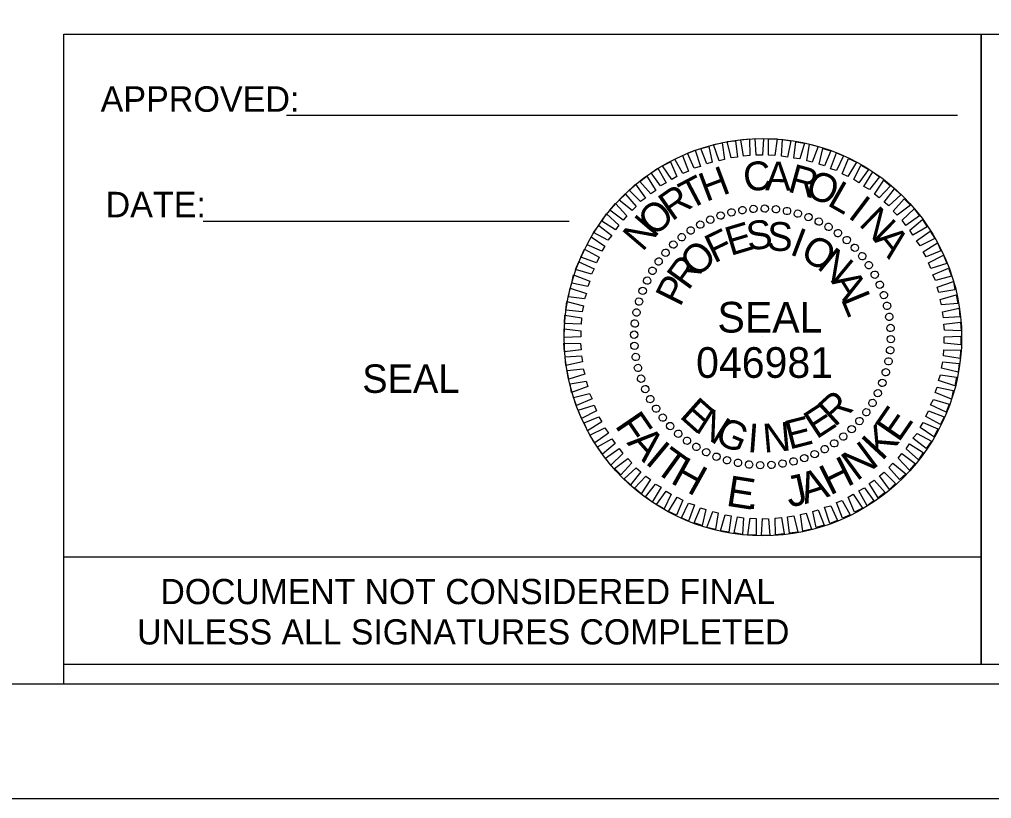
# Model space of a CAD drawing. Extents: x 2157572 to 5059327, y 715220 to 1674494.
# Drawn here: x 2166357 to 2168053, y 722289 to 723649 of the extents above; entities that cross this region are included whole.
import ezdxf

# ---------------------------------------------------------------- set-up
doc = ezdxf.new("R2010")
doc.units = 0
for name, color, linetype in [('Exist Road Primary NC Mileage Hundredths English Label', 7, 'Continuous'), ('Exist Road Secondary Type 51 Divided Label', 7, 'Continuous'), ('Exist Road Secondary Type 51 Undivided 3 Lane Attributed', 7, 'Continuous'), ('Map Preparation County Base Legend Wide River or Creek', 7, 'Continuous'), ('Map Preparation County North Arrow White Shapes', 7, 'Continuous')]:
    doc.layers.add(name, color=color, linetype=linetype)

# ---------------------------------------------------------------- blocks, each defined once
blk = doc.blocks.new('STICKER EXCEPTION CERTIFICATION')
at = {"layer": 'Map Preparation County Base Legend Wide River or Creek'}
for p, q in [((0, -0.188), (0, 0)), ((0, 0), (1.6003, 0)), ((1.6003, -0.0001), (1.6003, -0.1881)), ((1.6003, -0.188), (0, -0.188))]:
    blk.add_line(p, q, dxfattribs=at)
for s, p in [('DOCUMENT NOT CONSIDERED FINAL', (0.1686, -0.0828)), ('UNLESS ALL SIGNATURES COMPLETED', (0.128, -0.1532))]:
    blk.add_text(s, height=0.044, dxfattribs=at).set_placement(p)

msp = doc.modelspace()

# ---------------------------------------------------------------- linework, layer by layer
at = {"layer": 'Exist Road Primary NC Mileage Hundredths English Label'}
for p, q in [((2167580, 723306.6), (2167580, 723306.6)), ((2167598.8, 723311.9), (2167598.8, 723311.9)), ((2167618.4, 723315.5), (2167618.4, 723315.5)), ((2167637.6, 723318.2), (2167637.6, 723318.2)), ((2167657.3, 723318.6), (2167657.3, 723318.6)), ((2167676.9, 723317.3), (2167676.9, 723317.3)), ((2167696.1, 723314.2), (2167696.1, 723314.2)), ((2167714.9, 723310.2), (2167714.9, 723310.2)), ((2167544.8, 723290.5), (2167544.8, 723290.5)), ((2167562.2, 723299.4), (2167562.2, 723299.4)), ((2167733.6, 723303.9), (2167733.6, 723303.9)), ((2167751.5, 723295.9), (2167751.5, 723295.9)), ((2167527.8, 723280.2), (2167527.8, 723280.2)), ((2167768.9, 723286.9), (2167768.9, 723286.9)), ((2167785, 723275.8), (2167785, 723275.8)), ((2167497.4, 723255.7), (2167497.4, 723255.7)), ((2167512.2, 723269.1), (2167512.2, 723269.1)), ((2167800.6, 723263.7), (2167800.6, 723263.7)), ((2167484, 723241.8), (2167484, 723241.8)), ((2167814.4, 723250.3), (2167814.4, 723250.3)), ((2167472, 723226.2), (2167472, 723226.2)), ((2167827.8, 723235.6), (2167827.8, 723235.6)), ((2167839, 723220), (2167839, 723220)), ((2167460.8, 723210.1), (2167460.8, 723210.1)), ((2167849.3, 723203), (2167849.3, 723203)), ((2167451.9, 723192.7), (2167451.9, 723192.7)), ((2167443.9, 723174.9), (2167443.9, 723174.9)), ((2167858.2, 723185.6), (2167858.2, 723185.6)), ((2167437.6, 723156.1), (2167437.6, 723156.1)), ((2167865.3, 723167.7), (2167865.3, 723167.7)), ((2167433.6, 723137.4), (2167433.6, 723137.4)), ((2167870.7, 723149), (2167870.7, 723149)), ((2167430.5, 723118.2), (2167430.5, 723118.2)), ((2167874.3, 723129.3), (2167874.3, 723129.3)), ((2167876.9, 723110.1), (2167876.9, 723110.1)), ((2167429.1, 723098.5), (2167429.1, 723098.5)), ((2167653.3, 723094.5), (2167653.3, 723094.5)), ((2167877.4, 723090.5), (2167877.4, 723090.5)), ((2167429.6, 723078.9), (2167429.6, 723078.9)), ((2167876, 723070.8), (2167876, 723070.8)), ((2167432.2, 723059.7), (2167432.2, 723059.7)), ((2167872.9, 723051.6), (2167872.9, 723051.6)), ((2167435.8, 723040), (2167435.8, 723040)), ((2167441.2, 723021.3), (2167441.2, 723021.3)), ((2167868.9, 723032.9), (2167868.9, 723032.9)), ((2167448.3, 723003.4), (2167448.3, 723003.4)), ((2167862.7, 723014.1), (2167862.7, 723014.1)), ((2167457.2, 722986), (2167457.2, 722986)), ((2167854.6, 722996.3), (2167854.6, 722996.3)), ((2167467.5, 722969), (2167467.5, 722969)), ((2167845.7, 722978.9), (2167845.7, 722978.9)), ((2167478.7, 722953.4), (2167478.7, 722953.4)), ((2167834.5, 722962.8), (2167834.5, 722962.8)), ((2167492.1, 722938.7), (2167492.1, 722938.7)), ((2167809.1, 722933.3), (2167809.1, 722933.3)), ((2167822.5, 722947.2), (2167822.5, 722947.2)), ((2167505.9, 722925.3), (2167505.9, 722925.3)), ((2167794.3, 722919.9), (2167794.3, 722919.9)), ((2167521.5, 722913.2), (2167521.5, 722913.2)), ((2167537.6, 722902.1), (2167537.6, 722902.1)), ((2167761.7, 722898.5), (2167761.7, 722898.5)), ((2167778.7, 722908.8), (2167778.7, 722908.8)), ((2167555, 722893.1), (2167555, 722893.1)), ((2167572.9, 722885.1), (2167572.9, 722885.1)), ((2167726.5, 722882.4), (2167726.5, 722882.4)), ((2167744.3, 722889.6), (2167744.3, 722889.6)), ((2167591.6, 722878.9), (2167591.6, 722878.9)), ((2167610.4, 722874.8), (2167610.4, 722874.8)), ((2167629.6, 722871.7), (2167629.6, 722871.7)), ((2167649.2, 722870.4), (2167649.2, 722870.4)), ((2167668.9, 722870.8), (2167668.9, 722870.8)), ((2167688.1, 722873.5), (2167688.1, 722873.5)), ((2167707.7, 722877.1), (2167707.7, 722877.1))]:
    msp.add_line(p, q, dxfattribs=at)
for points in [[(2167642.5, 723411.9), (2167640.3, 723441), (2167655, 723440.5), (2167653.3, 723411.5)], [(2167664, 723411.5), (2167664, 723440.5), (2167678.7, 723440.1), (2167674.7, 723411.1)], [(2167555.9, 723396.3), (2167545.7, 723423.1), (2167559.5, 723427.1), (2167565.3, 723399.4)], [(2167577.4, 723402.1), (2167568, 723430.3), (2167583.2, 723433.4), (2167586.7, 723404.4)], [(2167598.8, 723407), (2167591.6, 723435.6), (2167606.4, 723437), (2167609.5, 723408.4)], [(2167620.2, 723409.7), (2167615.3, 723438.3), (2167630.5, 723440.1), (2167630.9, 723411.1)], [(2167686.3, 723410.2), (2167688.1, 723439.2), (2167702.8, 723436.5), (2167697, 723408.4)], [(2167707.7, 723406.6), (2167711.7, 723435.2), (2167726.5, 723432.9), (2167718.4, 723405.3)], [(2167730.5, 723401.7), (2167735, 723430.7), (2167750.1, 723427.1), (2167739.9, 723399.4)], [(2167751.9, 723395.9), (2167758.6, 723423.6), (2167772.5, 723419.1), (2167761.3, 723392.8)], [(2167514.4, 723379.8), (2167500.1, 723404.8), (2167514, 723411.1), (2167524.2, 723383.8)], [(2167534, 723389.2), (2167522.4, 723415.1), (2167535.8, 723420.4), (2167545.2, 723391.9)], [(2167772, 723387.8), (2167782.3, 723416), (2167794.8, 723410.6), (2167782.3, 723384.7)], [(2167495.2, 723369.1), (2167478.7, 723393.2), (2167492.5, 723400.3), (2167503.7, 723374.4)], [(2167792.1, 723379.4), (2167803.3, 723405.7), (2167817.1, 723399.4), (2167801.9, 723374.4)], [(2167812.6, 723369.1), (2167824.7, 723394.5), (2167838.1, 723386.9), (2167821.1, 723363.7)], [(2167458.6, 723344.5), (2167439.4, 723366), (2167451.4, 723375.3), (2167467.1, 723350.3)], [(2167475.6, 723357.9), (2167459, 723380.7), (2167470.6, 723389.2), (2167485.4, 723363.3)], [(2167830.1, 723357), (2167845.7, 723382.9), (2167857.3, 723373.6), (2167839.9, 723351.7)], [(2167440.7, 723330.7), (2167421.1, 723350.3), (2167431.8, 723361.1), (2167449.2, 723336.9)], [(2167848.4, 723343.6), (2167864.9, 723368.2), (2167876.5, 723358.4), (2167856.8, 723337.4)], [(2167426, 723315.1), (2167403.2, 723333.4), (2167414.4, 723343.6), (2167433.1, 723322.2)], [(2167865.3, 723329.8), (2167883.6, 723353), (2167894.4, 723342.3), (2167873.8, 723323.1)], [(2167410.4, 723298.1), (2167387.2, 723315.5), (2167397, 723327.1), (2167416.6, 723306.1)], [(2167881.4, 723314.2), (2167900.6, 723335.2), (2167911.3, 723324.4), (2167888.1, 723307)], [(2167397, 723281.1), (2167372.9, 723296.3), (2167381.3, 723309.3), (2167402.8, 723289.6)], [(2167897, 723298.1), (2167917.6, 723318.2), (2167926.9, 723306.1), (2167903.3, 723289.2)], [(2167383.6, 723263.3), (2167358.6, 723276.7), (2167367.5, 723289.2), (2167390.7, 723271.3)], [(2167910.4, 723280.7), (2167932.3, 723299.4), (2167940.8, 723286.5), (2167915.8, 723272.2)], [(2167922, 723262.4), (2167945.7, 723279.3), (2167954.2, 723266), (2167928.3, 723253.5)], [(2167372.9, 723244.1), (2167347.4, 723255.2), (2167354.1, 723269.1), (2167378.2, 723252.6)], [(2167933.6, 723242.7), (2167958.6, 723258.4), (2167964.4, 723244.5), (2167939, 723234.3)], [(2167363.9, 723223.5), (2167336.3, 723233.8), (2167343, 723247.6), (2167368.4, 723233.4)], [(2167942.6, 723223.5), (2167968.9, 723236.9), (2167974.7, 723222.6), (2167947, 723213.7)], [(2167355, 723203.9), (2167327.3, 723211.9), (2167333.1, 723225.8), (2167359.9, 723213.3)], [(2167348.3, 723182.5), (2167320.6, 723188.3), (2167323.8, 723203), (2167351.9, 723191.8)], [(2167950.6, 723202.6), (2167977.8, 723214.2), (2167982.8, 723200.3), (2167955.1, 723193.2)], [(2167957.8, 723181.1), (2167986.3, 723191.4), (2167989, 723176.7), (2167960.9, 723171.7)], [(2167342.5, 723161), (2167314.8, 723164.6), (2167317.9, 723179.8), (2167346.1, 723170.4)], [(2167338.9, 723138.3), (2167310.4, 723140.9), (2167312.1, 723156.1), (2167341.2, 723149)], [(2167963.1, 723159.7), (2167991.2, 723168.2), (2167993.9, 723153), (2167965.8, 723150.3)], [(2167967.1, 723138.3), (2167996.1, 723144.5), (2167997.5, 723129.3), (2167968.9, 723127.5)], [(2167336.7, 723116.8), (2167307.7, 723117.7), (2167308.6, 723132.5), (2167337.6, 723127.5)], [(2167969.8, 723116.8), (2167998.8, 723120.4), (2167999.7, 723105.2), (2167970.7, 723106.1)], [(2167336.3, 723094.5), (2167307.2, 723093.2), (2167307.2, 723108.3), (2167336.3, 723105.2)], [(2167970.3, 723094.5), (2167999.3, 723095.8), (2167999.3, 723080.7), (2167970.3, 723083.8)], [(2167336.7, 723072.2), (2167307.7, 723068.6), (2167306.8, 723083.8), (2167335.8, 723082.9)], [(2167969.8, 723072.2), (2167998.8, 723071.3), (2167997.9, 723056.6), (2167968.9, 723061.5)], [(2167339.4, 723050.7), (2167310.4, 723044.5), (2167309, 723059.7), (2167337.6, 723061.5)], [(2167967.6, 723050.7), (2167996.1, 723048.1), (2167994.4, 723032.9), (2167965.3, 723040)], [(2167343.4, 723029.3), (2167315.3, 723020.8), (2167312.6, 723036), (2167340.7, 723038.7)], [(2167348.8, 723007.9), (2167320.2, 722997.6), (2167317.5, 723012.4), (2167345.6, 723017.3)], [(2167964, 723028), (2167991.7, 723024.4), (2167988.6, 723009.2), (2167960.4, 723018.6)], [(2167958.2, 723006.5), (2167985.9, 723000.7), (2167982.8, 722986), (2167954.6, 722997.2)], [(2167355.9, 722986.5), (2167328.7, 722974.8), (2167323.8, 722988.7), (2167351.4, 722995.8)], [(2167951.5, 722985.1), (2167979.2, 722977.1), (2167973.4, 722963.2), (2167946.6, 722975.7)], [(2167363.9, 722965.5), (2167337.6, 722952.1), (2167331.8, 722966.4), (2167359.5, 722975.3)], [(2167942.6, 722965.5), (2167970.3, 722955.2), (2167963.6, 722941.4), (2167938.1, 722955.6)], [(2167372.9, 722946.3), (2167347.9, 722930.6), (2167342.1, 722944.5), (2167367.5, 722954.8)], [(2167384.5, 722926.6), (2167360.8, 722909.7), (2167352.3, 722923.1), (2167378.2, 722935.6)], [(2167933.6, 722944.9), (2167959.1, 722933.8), (2167952.4, 722919.9), (2167928.3, 722936.5)], [(2167396.1, 722908.3), (2167374.2, 722889.6), (2167365.7, 722902.5), (2167390.7, 722916.8)], [(2167922.9, 722925.7), (2167947.9, 722912.3), (2167939, 722899.8), (2167915.8, 722917.7)], [(2167409.5, 722890.9), (2167388.9, 722870.8), (2167379.6, 722882.9), (2167403.2, 722899.8)], [(2167909.5, 722907.9), (2167933.6, 722892.7), (2167925.2, 722879.7), (2167903.7, 722899.4)], [(2167425.1, 722874.8), (2167405.9, 722853.9), (2167395.2, 722864.6), (2167418.4, 722882)], [(2167896.1, 722890.9), (2167919.4, 722873.5), (2167909.5, 722861.9), (2167889.9, 722882.9)], [(2167441.2, 722859.2), (2167422.9, 722836), (2167412.2, 722846.7), (2167432.7, 722865.9)], [(2167880.5, 722873.9), (2167903.3, 722855.6), (2167892.1, 722845.4), (2167873.4, 722866.8)], [(2167458.1, 722845.4), (2167441.6, 722820.8), (2167430, 722830.6), (2167449.7, 722851.6)], [(2167865.8, 722858.3), (2167885.4, 722838.7), (2167874.7, 722828), (2167857.3, 722852.1)], [(2167476.4, 722832), (2167460.8, 722806.1), (2167449.2, 722815.5), (2167466.6, 722837.3)], [(2167831, 722831.1), (2167847.5, 722808.3), (2167835.9, 722799.8), (2167821.1, 722825.7)], [(2167847.9, 722844.5), (2167867.1, 722823), (2167855.1, 722813.7), (2167839.4, 722838.7)], [(2167493.9, 722819.9), (2167481.8, 722794.5), (2167468.4, 722802.1), (2167485.4, 722825.3)], [(2167514.4, 722809.7), (2167503.2, 722783.3), (2167489.4, 722789.6), (2167504.6, 722814.6)], [(2167811.3, 722819.9), (2167827.8, 722795.8), (2167814, 722788.7), (2167802.8, 722814.6)], [(2167534.5, 722801.2), (2167524.2, 722773), (2167511.7, 722778.4), (2167524.2, 722804.3)], [(2167554.6, 722793.1), (2167547.9, 722765.4), (2167534, 722769.9), (2167545.2, 722796.3)], [(2167772.5, 722799.8), (2167784.1, 722773.9), (2167770.7, 722768.6), (2167761.3, 722797.1)], [(2167792.1, 722809.2), (2167806.4, 722784.2), (2167792.6, 722778), (2167782.3, 722805.2)], [(2167576, 722787.3), (2167571.5, 722758.3), (2167556.4, 722761.9), (2167566.6, 722789.6)], [(2167598.8, 722782.4), (2167594.8, 722753.8), (2167580, 722756.1), (2167588.1, 722783.8)], [(2167620.2, 722778.8), (2167618.4, 722749.8), (2167603.7, 722752.5), (2167609.5, 722780.6)], [(2167686.3, 722779.3), (2167691.2, 722750.7), (2167676, 722748.9), (2167675.6, 722778)], [(2167707.7, 722782), (2167714.9, 722753.4), (2167700.1, 722752.1), (2167697, 722780.6)], [(2167729.2, 722786.9), (2167738.5, 722758.8), (2167723.4, 722755.6), (2167719.8, 722784.6)], [(2167750.6, 722792.7), (2167760.9, 722765.9), (2167747, 722761.9), (2167741.2, 722789.6)], [(2167642.5, 722777.5), (2167642.5, 722748.5), (2167627.8, 722748.9), (2167631.8, 722778)], [(2167664, 722777.1), (2167666.2, 722748), (2167651.5, 722748.5), (2167653.3, 722777.5)]]:
    msp.add_lwpolyline(points, close=True, dxfattribs=at)
for centre, major_axis in [((2167618.2, 723315.7), (-1.01, 6.35)), ((2167637.6, 723317.9), (-0.45, 6.41)), ((2167657.2, 723318.4), (0.11, 6.43)), ((2167676.7, 723317.2), (0.67, 6.39)), ((2167562.2, 723299.1), (-2.62, 5.87)), ((2167580.3, 723306.3), (-2.09, 6.08)), ((2167599.1, 723311.8), (-1.56, 6.24)), ((2167696, 723314.3), (1.23, 6.31)), ((2167715, 723309.8), (1.77, 6.18)), ((2167733.5, 723303.6), (2.3, 6)), ((2167528, 723280.2), (-3.6, 5.33)), ((2167544.7, 723290.4), (-3.12, 5.62)), ((2167751.4, 723295.8), (2.82, 5.78)), ((2167768.6, 723286.5), (3.31, 5.51)), ((2167512.3, 723268.5), (-4.05, 5)), ((2167784.9, 723275.7), (3.78, 5.2)), ((2167800.2, 723263.5), (4.22, 4.85)), ((2167497.7, 723255.6), (-4.47, 4.62)), ((2167814.4, 723250.1), (4.62, 4.47)), ((2167484.2, 723241.4), (-4.85, 4.22)), ((2167827.3, 723235.4), (5, 4.05)), ((2167472.1, 723226.1), (-5.2, 3.78)), ((2167838.9, 723219.7), (5.33, 3.6)), ((2167461.3, 723209.8), (-5.51, 3.31)), ((2167849.1, 723203.1), (5.62, 3.12)), ((2167452, 723192.7), (-5.78, 2.82)), ((2167857.8, 723185.6), (5.87, 2.62)), ((2167444.2, 723174.8), (-6, 2.3)), ((2167865, 723167.4), (6.08, 2.09)), ((2167438, 723156.2), (-6.18, 1.77)), ((2167870.6, 723148.7), (6.24, 1.56)), ((2167433.4, 723137.2), (-6.31, 1.23)), ((2167874.4, 723129.5), (6.35, 1.01)), ((2167430.5, 723117.9), (-6.39, 0.67)), ((2167429.3, 723098.4), (-6.43, 0.11)), ((2167876.7, 723110.1), (6.41, 0.45)), ((2167429.8, 723078.9), (-6.41, -0.45)), ((2167877.2, 723090.6), (6.43, -0.11)), ((2167876, 723071.1), (6.39, -0.67)), ((2167432.1, 723059.5), (-6.35, -1.01)), ((2167873.1, 723051.8), (6.31, -1.23)), ((2167436, 723040.3), (-6.24, -1.56)), ((2167868.5, 723032.8), (6.18, -1.77)), ((2167441.5, 723021.6), (-6.08, -2.09)), ((2167862.3, 723014.2), (6, -2.3)), ((2167448.7, 723003.4), (-5.87, -2.62)), ((2167854.5, 722996.3), (5.78, -2.82)), ((2167457.4, 722985.9), (-5.62, -3.12)), ((2167845.2, 722979.2), (5.51, -3.31)), ((2167467.6, 722969.3), (-5.33, -3.6)), ((2167834.4, 722962.9), (5.2, -3.78)), ((2167479.2, 722953.6), (-5, -4.05)), ((2167822.3, 722947.6), (4.85, -4.22)), ((2167492.2, 722938.9), (-4.62, -4.47)), ((2167506.3, 722925.5), (-4.22, -4.85)), ((2167808.8, 722933.4), (4.47, -4.62)), ((2167521.6, 722913.3), (-3.78, -5.2)), ((2167778.5, 722908.8), (3.6, -5.33)), ((2167794.2, 722920.5), (4.05, -5)), ((2167537.9, 722902.5), (-3.31, -5.51)), ((2167555.1, 722893.2), (-2.82, -5.78)), ((2167761.8, 722898.6), (3.12, -5.62)), ((2167573, 722885.4), (-2.3, -6)), ((2167591.5, 722879.2), (-1.77, -6.18)), ((2167610.5, 722874.7), (-1.23, -6.31)), ((2167707.4, 722877.2), (1.56, -6.24)), ((2167726.2, 722882.8), (2.09, -6.08)), ((2167744.3, 722889.9), (2.62, -5.87)), ((2167629.8, 722871.8), (-0.67, -6.39)), ((2167649.3, 722870.6), (-0.11, -6.43)), ((2167668.9, 722871.1), (0.45, -6.41)), ((2167688.3, 722873.3), (1.01, -6.35))]:
    msp.add_ellipse(centre, major_axis=major_axis, ratio=0.999708, dxfattribs=at)
at = {"layer": 'Exist Road Secondary Type 51 Divided Label'}
msp.add_lwpolyline([(2157571.9, 722288.7), (2171075.9, 722288.7), (2171075.9, 731088.6), (2157571.9, 731088.6)], close=True, dxfattribs=at)
at = {"layer": 'Exist Road Secondary Type 51 Undivided 3 Lane Attributed'}
msp.add_lwpolyline([(2170485.5, 727897.1), (2170495.8, 729042.7), (2158875.9, 729042.7), (2158875.9, 722488.7), (2166434.4, 722488.7), (2166434.4, 723622.8), (2170875.9, 723622.8), (2170875.9, 727897.1)], close=True, dxfattribs=at)
at = {"layer": 'Map Preparation County North Arrow White Shapes'}
for p, q in [((2166822.8, 723481.4), (2167993.5, 723481.4)), ((2168034.7, 723434.8), (2168034.7, 722522.8)), ((2166677.8, 723296.7), (2167316.2, 723296.7))]:
    msp.add_line(p, q, dxfattribs=at)
for points in [[(2170875.9, 730888.7), (2158875.9, 730888.7), (2158875.9, 722488.7), (2170875.9, 722488.7)], [(2166434.4, 723622.8), (2168034.7, 723622.8), (2168034.7, 722522.8), (2166434.4, 722522.8)], [(2168034.7, 723622.8), (2168946.7, 723622.8), (2168946.7, 722522.8), (2168034.7, 722522.8)]]:
    msp.add_lwpolyline(points, close=True, dxfattribs=at)
msp.add_circle((2167653.9, 723094.1), 346.7, dxfattribs=at)

# ---------------------------------------------------------------- block references
at = {"layer": 'Map Preparation County North Arrow White Shapes', "xscale": 999.998, "yscale": 999.998}
msp.add_blockref('STICKER EXCEPTION CERTIFICATION', (2166434.4, 722710.8), dxfattribs=at)

# ---------------------------------------------------------------- texts
at = {"layer": 'Exist Road Primary NC Mileage Hundredths English Label'}
for s, height, rotation, p in [('H', 50.3, 20.6195, (2167554.6, 723329.8)), ('C', 50.3, 6.2199, (2167622.4, 723347.7)), ('A', 50.3, 359.0203, (2167657.7, 723350.3)), ('R', 50.3, 344.6211, (2167695.2, 723348.6)), ('T', 50.3, 27.8198, (2167525.6, 723315.1)), ('O', 50.3, 337.4212, (2167725.1, 723341.9)), ('R', 50.3, 35.0205, (2167495.2, 723295.4)), ('L', 50.3, 330.2209, (2167764.4, 723325.3)), ('I', 50.3, 323.0201, (2167800.6, 723303.9)), ('O', 50.3, 42.2217, (2167464.4, 723267.7)), ('N', 50.4, 315.8189, (2167819.8, 723290.1)), ('N', 50.4, 49.4235, (2167443.9, 723241.8)), ('E', 50.3, 16.6111, (2167597.4, 723235.6)), ('S', 50.3, 7.2556, (2167628.3, 723245)), ('S', 50.3, 357.9004, (2167660.4, 723245.4)), ('F', 50.3, 25.967, (2167568.9, 723222.2)), ('I', 50.3, 339.1896, (2167698.8, 723239.2)), ('A', 50.4, 308.6172, (2167846.1, 723263.7)), ('O', 50.4, 44.6812, (2167539.4, 723195.9)), ('O', 50.3, 329.8335, (2167716.7, 723232.9)), ('N', 50.3, 320.4766, (2167746.6, 723215.1)), ('R', 50.4, 54.0397, (2167523.8, 723174)), ('P', 50.4, 63.3989, (2167509.5, 723145.4)), ('A', 50.4, 301.7603, (2167772, 723191.8)), ('L', 50.4, 292.4009, (2167789.4, 723161)), ('SEAL', 53.56, 360, (2167574.7, 723102.1)), ('E', 50.3, 318.2769, (2167506.8, 722954.8)), ('R', 50.4, 42.4814, (2167779.2, 722936)), ('N', 50.3, 327.634, (2167533.6, 722930.6)), ('E', 50.3, 33.1241, (2167747.5, 722915)), ('E', 53.6, 55.493, (2167890.8, 722908.8)), ('F', 53.6, 304.4142, (2167394.6, 722939.6)), ('G', 50.3, 336.9902, (2167567.5, 722910.6)), ('E', 50.3, 14.4118, (2167700.1, 722897.6)), ('I', 50.3, 355.7012, (2167626, 722893.6)), ('N', 50.3, 5.0564, (2167655.9, 722892.2)), ('K', 53.6, 47.2091, (2167861.6, 722876.6)), ('A', 53.6, 311.4309, (2167415.4, 722909.2)), ('I', 53.6, 320.2712, (2167446.7, 722874.8)), ('T', 53.6, 324.0731, (2167461.8, 722861.6)), ('N', 53.6, 36.4833, (2167817.4, 722841.6)), ('H', 53.6, 330.8733, (2167490.7, 722840.6)), ('H', 53.6, 26.4993, (2167771, 722817)), ('E', 53.6, 351.0577, (2167588.3, 722800.1)), ('J', 53.6, 12.4012, (2167699.9, 722796.6)), ('A', 53.6, 17.659, (2167727, 722802.2)), ('.', 53.6, 358.167, (2167625.2, 722794.3))]:
    msp.add_text(s, height=height, rotation=rotation, dxfattribs=at).set_placement(p)
msp.add_text('046981', height=53.56, dxfattribs=at).set_placement((2167537.4, 723023))
at = {"layer": 'Map Preparation County North Arrow White Shapes'}
for s, height, p in [('APPROVED:  ', 44.453, (2166498.6, 723487.4)), ('DATE:  ', 44.45, (2166507.3, 723303.3)), ('SEAL', 49.62, (2166955, 722996.8))]:
    msp.add_text(s, height=height, dxfattribs=at).set_placement(p)

doc.saveas('drawing.dxf')
